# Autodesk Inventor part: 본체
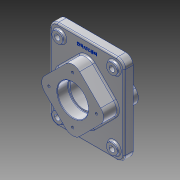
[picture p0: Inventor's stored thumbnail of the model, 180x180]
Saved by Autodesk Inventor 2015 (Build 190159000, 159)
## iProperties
Created: 2026-07
Part Number: 본체
Material: 알루미늄 6061
Document SubType Name: Modeling
Designer: USER
Mass: 2132.41 g
Surface Area: 955.114 cm^2
Volume: 789.782 cm^3
Density: 2.7 g/cm^3
Appearance: 알루미늄 - 평지
Author: USER
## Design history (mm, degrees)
sketch "스케치1"
  geometry: L1 (75, -90)-(-75, -90); L2 (-75, -90)-(-75, 90); L3 (-75, 90)-(75, 90); L4 (75, 90)-(75, -90); L5 (75, -90)-(-75, 90); L6 (-75, -90)-(75, 90); 1 further point
  constraints: 12 end point, 2 midpoint, 2 parallel, 1 horizontal, 1 perpendicular
  dimensions: "d0" = 150 distance of L2.end L3.end; "d1" = 180 distance of L1.end L2.end
extrude "돌출1" new body sketch "스케치1" stored distance "d2" = 18; taper "d3" = 0 deg
sketch "스케치2"
  geometry: L1 (0, -70.711)-(-70.711, 0); L2 (-70.711, 0)-(0, 70.711); L3 (0, 70.711)-(70.711, 0); L4 (70.711, 0)-(0, -70.711); 2 further points
  constraints: 8 end point, 1 coincident, 1 vertical alignment, 9 other
  dimensions: "d4" = 100 distance of L2.end L3.end
extrude "돌출2" join sketch "스케치2" distance "d5" = 29; taper "d6" = 0 deg; dims "d7" = 41, "d8" = 0
fillet "모깎기1" dims "d9" = 15
fillet "모깎기2" dims "d10" = 20
sketch "스케치3"
  geometry: L1 (-75, -75)-(-75, 75) reference; L2 (-60, 90)-(60, 90) reference; L3 (56.569, -14.142)-(14.142, -56.569) reference; L4 (-14.142, -56.569)-(-56.569, -14.142) reference; L5 (-56.569, 14.142)-(-14.142, 56.569) reference; L6 (14.142, 56.569)-(56.569, 14.142) reference; L7 (75, 75)-(75, -75) reference; L8 (60, -90)-(-60, -90) reference; L9 (-75, -75)-(-75, 75) reference; L10 (-60, 90)-(60, 90) reference; C1 r 11 at (-55, 70); A1 r 20 centre (42.426, 0) between (56.569, -14.142) and (56.569, 14.142) reference; A2 r 20 centre (0, -42.426) between (-14.142, -56.569) and (14.142, -56.569) reference; A3 r 20 centre (-42.426, 0) between (-56.569, 14.142) and (-56.569, -14.142) reference; A4 r 20 centre (0, 42.426) between (14.142, 56.569) and (-14.142, 56.569) reference; A5 r 15 centre (60, 75) between (75, 75) and (60, 90) reference; A6 r 15 centre (60, -75) between (60, -90) and (75, -75) reference; A7 r 15 centre (-60, -75) between (-75, -75) and (-60, -90) reference; A8 r 15 centre (-60, 75) between (-60, 90) and (-75, 75) reference; 1 further point
  constraints: 1 centre point
  dimensions: "d11" = 11 radius of C1; "d12" = 20 distance from line of C1.centre L1; "d13" = 20 distance from line of L10 C1.centre
extrude "돌출3" join sketch "스케치3" distance "d14" = 5; taper "d15" = 0 deg
hole "구멍1" diameter "d18" = 11; stored, may be unused: countersink angle "d22" = 90 deg, drill point angle "d24" = 118 deg; dims "d16" = 10, "d17" = 10, "d19" = 6, "d20" = 4, "d21" = 2, "d23" = 8
sketch "스케치4"
  geometry: 1 further point
hole "구멍2" sketch "스케치4" at (0, 0) diameter "d31" = 54; stored, may be unused: countersink angle "d35" = 90 deg, drill point angle "d37" = 118 deg; dims "d32" = 6, "d33" = 62, "d34" = 22, "d36" = 8
hole "구멍3" diameter "d40" = 62; stored, may be unused: countersink angle "d44" = 90 deg, drill point angle "d46" = 0 deg; dims "d38" = 10, "d39" = 10, "d41" = 6, "d42" = 62, "d43" = 22, "d45" = 22
sketch "스케치5"
  geometry: L1 (0, 0)-(0, 48)
  constraints: 2 end point, 1 vertical
  dimensions: "d47" = 48 distance of L1.start L1.end
hole "구멍4" sketch "스케치5" at (0, 48) diameter "d48" = 4.917; stored, may be unused: countersink angle "d52" = 90 deg, drill point angle "d54" = 118 deg; dims "d49" = 10, "d50" = 62, "d51" = 22, "d53" = 13
sketch "스케치6"
  geometry: L1 (0, 0)-(0, -48); C1 r 2.458 at (0, -48) reference
  constraints: 2 end point, 1 vertical
  dimensions: "d58" = 48 distance of L1.start L1.end (derived)
hole "구멍5" sketch "스케치6" at (0, -48) diameter "d59" = 4.917; stored, may be unused: countersink angle "d63" = 90 deg, drill point angle "d65" = 118 deg; dims "d60" = 10, "d61" = 62, "d62" = 22, "d64" = 13
sketch "스케치7"
  geometry: L1 (60, 90)-(-60, 90) reference; 2 further points
  constraints: 1 vertical alignment, 1 other
  dimensions: "d69" = 15 distance from line of point (0, 75) L1
feature "엠보싱1" sketch "스케치7" dims "d0" = 150, "d1" = 180, "d70" = 0.5, "d71" = 0
chamfer "모따기1" distance "d72" = 1; stored, may be unused: second distance "d73" = 2, angle "d74" = 45 deg
fillet "모깎기3" dims "d75" = 1
fillet "모깎기4" dims "d76" = 3
fillet "모깎기5" dims "d77" = 3
node "솔리드1"
pattern_linear "직사각형 패턴1"
pattern_circular "원형 패턴1" dims angle "d56" = 360 deg
pattern_circular "원형 패턴2" dims angle "d67" = 360 deg
node "절단 모서리 투영1"
